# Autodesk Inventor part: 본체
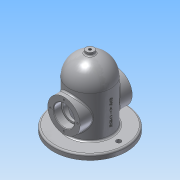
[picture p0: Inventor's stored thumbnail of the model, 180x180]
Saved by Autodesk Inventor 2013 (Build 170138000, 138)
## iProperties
Created: 2019-11
Part Number: 본체
Material: 알루미늄 6061
Document SubType Name: Modeling
Designer: Administrator
Density: 2.71 g/cm^3
Mass: 1110.22 g
Surface Area: 883.263 cm^2
Volume: 409.674 cm^3
Author: Administrator
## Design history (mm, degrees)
sketch "스케치1"
  geometry: L1 (0, 0)-(0, 130); L2 (0, 0)-(-40, 0); L3 (-40, 0)-(-40, 90); L4 (-40, 90)-(0, 90); A1 r 40 centre (0, 90) between (0, 130) and (0, 50); A2 r 40 centre (0, 90) between (0, 50) and (0, 130)
  constraints: 8 end point, 5 point on circle, 3 perpendicular, 2 centre point, 2 point on line, 1 coincident, 1 vertical
  dimensions: "d1" = 80 diameter of L3 L1; "d22" = 90 distance of L2.end L3.end
revolve "회전1" sketch "스케치1" stored, may be unused: angle "d2" = 90 deg
feature "쉘1" dims "d3" = 10
sketch "스케치2"
  geometry: C1 r 40 at (0, 0) reference; C2 r 70 at (0, 0)
  constraints: 1 centre point, 1 coincident
  dimensions: "d4" = 140 diameter of C2
extrude "돌출1" join sketch "스케치2" distance "d5" = 10; taper "d6" = 0 deg
node "작업 평면1"
sketch "스케치3"
  geometry: L1 (-48.99, 0)-(-48.99, 10) reference; L2 (-48.99, 10)-(48.99, 10) reference; L3 (48.99, 10)-(48.99, 0) reference; L4 (48.99, 0)-(-48.99, 0) reference; C1 r 31 at (0, 50); 2 further points
  constraints: 1 centre point, 1 midpoint, 1 vertical alignment
  dimensions: "d8" = 62 diameter of C1; "d9" = 50 distance from line of L4 C1.centre
extrude "돌출2" join sketch "스케치3" stored distance "d10" = 10; taper "d11" = 0 deg
sketch "스케치4"
  geometry: C1 r 31 at (0, 0) reference; C2 r 20 at (0, 0); 1 further point
  constraints: 1 centre point, 1 coincident
  dimensions: "d12" = 40 diameter of C2
extrude "돌출3" cut sketch "스케치4" distance "d13" = 15; taper "d14" = 0 deg
sketch "스케치5"
  geometry: C1 r 20 at (0, 0) reference; C2 r 16.5 at (0, 0); 1 further point
  constraints: 1 centre point, 1 coincident
  dimensions: "d15" = 33 diameter of C2
extrude "돌출4" cut sketch "스케치5" stored distance "d16" = 15; taper "d17" = 0 deg
node "작업 평면2"
sketch "스케치6"
  geometry: C1 r 7.5 at (0, 0); 1 further point
  constraints: 1 centre point, 1 coincident
  dimensions: "d19" = 15 diameter of C1
extrude "돌출5" join sketch "스케치6" stored distance "d20" = 15; taper "d21" = 0 deg
sketch "스케치7" dims "d23" = 52
  geometry: C1 r 31 at (0, 0) reference; 3 further points
  constraints: 2 vertical alignment, 1 coincident, 2 other
hole "구멍1" sketch "스케치7" at (0, 26) diameter "d24" = 3.242; stored, may be unused: countersink angle "d28" = 90 deg, drill point angle "d30" = 118 deg; dims "d25" = 8, "d26" = 4, "d27" = 2, "d29" = 10
sketch "스케치8" dims "d34" = 110
  geometry: C1 r 70 at (0, 0) reference; 2 further points
  constraints: 2 horizontal alignment, 1 coincident, 2 other
hole "구멍2" sketch "스케치8" at (55, 0) diameter "d35" = 9; stored, may be unused: countersink angle "d39" = 90 deg, drill point angle "d41" = 118 deg; dims "d36" = 8, "d37" = 4, "d38" = 2, "d40" = 10
sketch "스케치9"
  geometry: C1 r 7.5 at (0, 0) reference
hole "구멍3" sketch "스케치9" at (0, 0) diameter "d45" = 5.188; stored, may be unused: countersink angle "d49" = 90 deg, drill point angle "d51" = 118 deg; dims "d46" = 8, "d47" = 4, "d48" = 2, "d50" = 27.75
node "작업 평면3"
sketch "스케치10"
  geometry: L1 (70, 0)-(-70, 0) reference; 2 further points
  constraints: 1 vertical alignment, 1 other
  dimensions: "d53" = 50 distance from line of L1 point (0, 50)
feature "엠보싱1" sketch "스케치10" dims "d54" = 0.5, "d55" = 0
chamfer "모따기1" distance "d56" = 1; stored, may be unused: second distance "d57" = 2, angle "d58" = 45 deg
fillet "모깎기1" dims "d59" = 0.3
fillet "모깎기2" dims "d60" = 3
node "솔리드1"
mirror "대칭2"
pattern_circular "원형 패턴1" dims angle "d32" = 360 deg
mirror "대칭3"
pattern_circular "원형 패턴2" dims angle "d43" = 360 deg
node "절단 모서리 투영1"
other parameters: "d18" = -135, "d52" = 54.75
